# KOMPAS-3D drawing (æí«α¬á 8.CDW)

Referenced files: Редуктор-2.CDW
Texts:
  Редуктор цилиндрический  двуступенчатый
  Noncommercial version
  Normal
  min 35 мм
  min
  max
  aw б =
  aw т =
  Быстроходная ступень: m = ; z1 = 27; z2 = 96; b = 10,26
  Symbol type A
  Тихоходная ступень: m = 2,5; z1 = 32; z2 = 128; b = 0
  u = 14,22; nвх = 1455 об/мин; nвых = 102,304 об/мин;  Tвых = 1318959,012 Н мм
  1. Корпус редуктора грунтовать и покрасить внутри и снаружи
  2. При сборке плоскость разъёма покрыть герметиком.
  3. В редуктор залить масло И - 40А ГОСТ 20799-75 в объёме 13,4 л
  4. Камеры подшинпиков заполнить смазкой ЦИАТИМ - 201 ГОСТ 6267 - 74
  5. Редуктор обкатать по ТУ завода-изготовителя.
  Редуктор цилиндрический
  двуступенчатый
Dimensions and other numbers on the sheet: 21; 45; 36; 16,5; 420; 296; 342; 252; 62; 75; 110; 35; 48; 60; 58; 70; 212; 16; 607; 550; 505; 25; 18; 14; 125; 200; 494; 5; 12; 66,47; 28; 38; 24; 23; 26; 39; 17; 1; 34; 29; 33; 11; 44; 41; 19; 30; 2; 32; 43; 27; 37; 20; 4; 31; 15; 22; 42; 3; 40; 53; 1:1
